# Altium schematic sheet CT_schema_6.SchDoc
size 304 x 256 mm
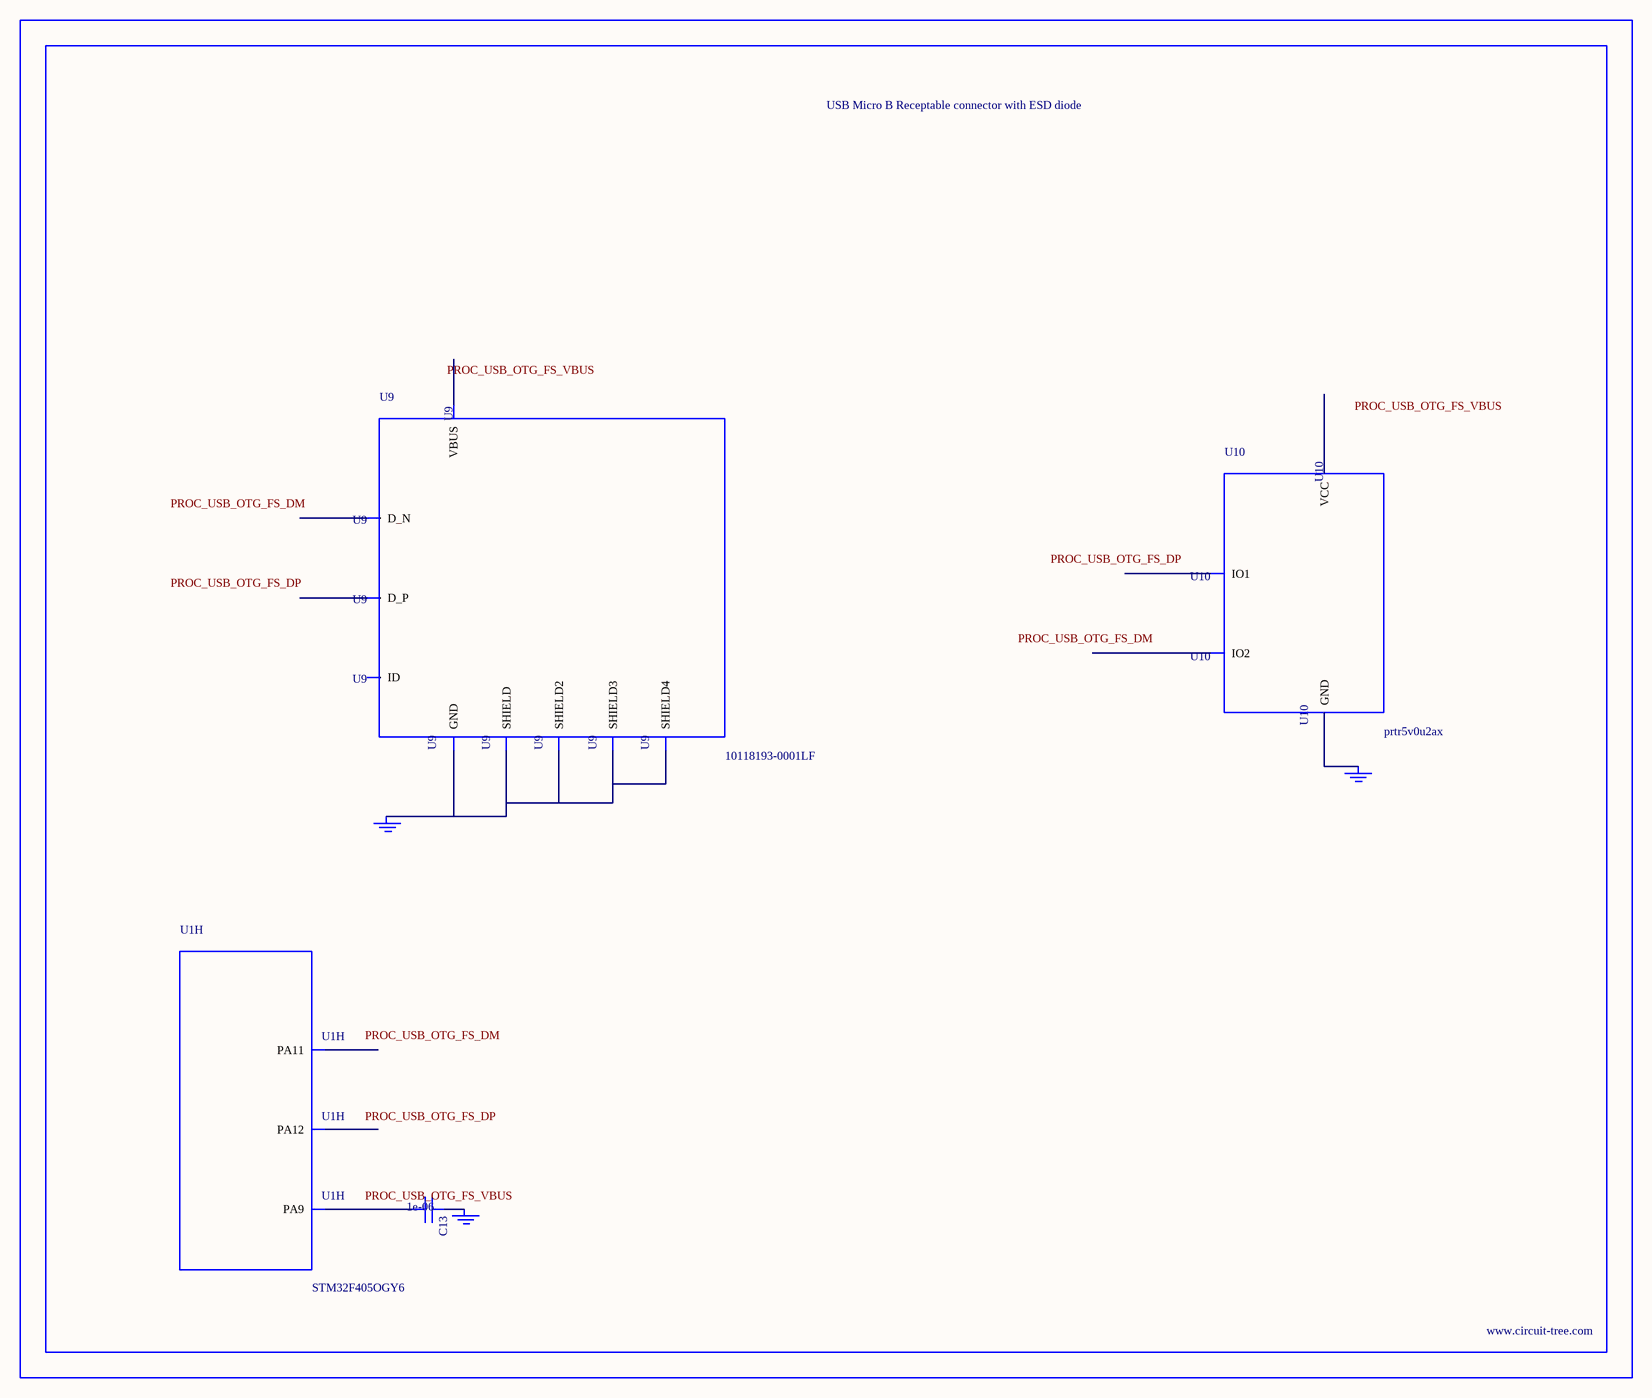
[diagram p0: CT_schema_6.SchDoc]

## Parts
BORDER5  (no value)
C13  1e-06  [C0603]
GND_INSTANCE_5_0  (no value)
GND_INSTANCE_5_1  (no value)
GND_INSTANCE_5_2  (no value)
U1  STM32F405OGY6  [WLCSP90]  (part H of 9)
U9  10118193-0001LF  [FCI_10118193-0001LF]
U10  prtr5v0u2ax  [SOT143B]

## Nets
NetC13_1: C13.1 GND_INSTANCE_5_1.0(GND)
NetC13_2: C13.2 U1.D2(PA9)
NetGND_INSTANCE_5_0_0: GND_INSTANCE_5_0.0(GND) U9.5(GND) U9.6(SHIELD) U9.7(SHIELD2) U9.8(SHIELD3) U9.9(SHIELD4)
NetGND_INSTANCE_5_2_0: GND_INSTANCE_5_2.0(GND) U10.1(GND)

Not connected (* = marked no-connect by the designer): U1 C1(PA11) C2(PA12); U9 1(VBUS) 2(D_N) 3(D_P) 4(ID); U10 2(IO1) 3(IO2) 4(VCC)

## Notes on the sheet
- Labels drawn without touching a wire or pin: PROC_USB_OTG_FS_DM, PROC_USB_OTG_FS_DP, PROC_USB_OTG_FS_VBUS

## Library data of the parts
BORDER5 = BORDER_PAGE5
C13 = C0603C105K3RACTU
GND_INSTANCE_5_0-GND_INSTANCE_5_2 = GND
